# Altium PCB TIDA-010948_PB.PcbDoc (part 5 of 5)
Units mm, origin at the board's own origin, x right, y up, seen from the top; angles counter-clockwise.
Board outline 140 x 180 mm, 4 copper layers (Top Layer, Mid-Layer 1, Mid-Layer 2, Bottom Layer), stack 1.554 mm thick; 481 components, 274 nets, 1278 pads, 301 vias.
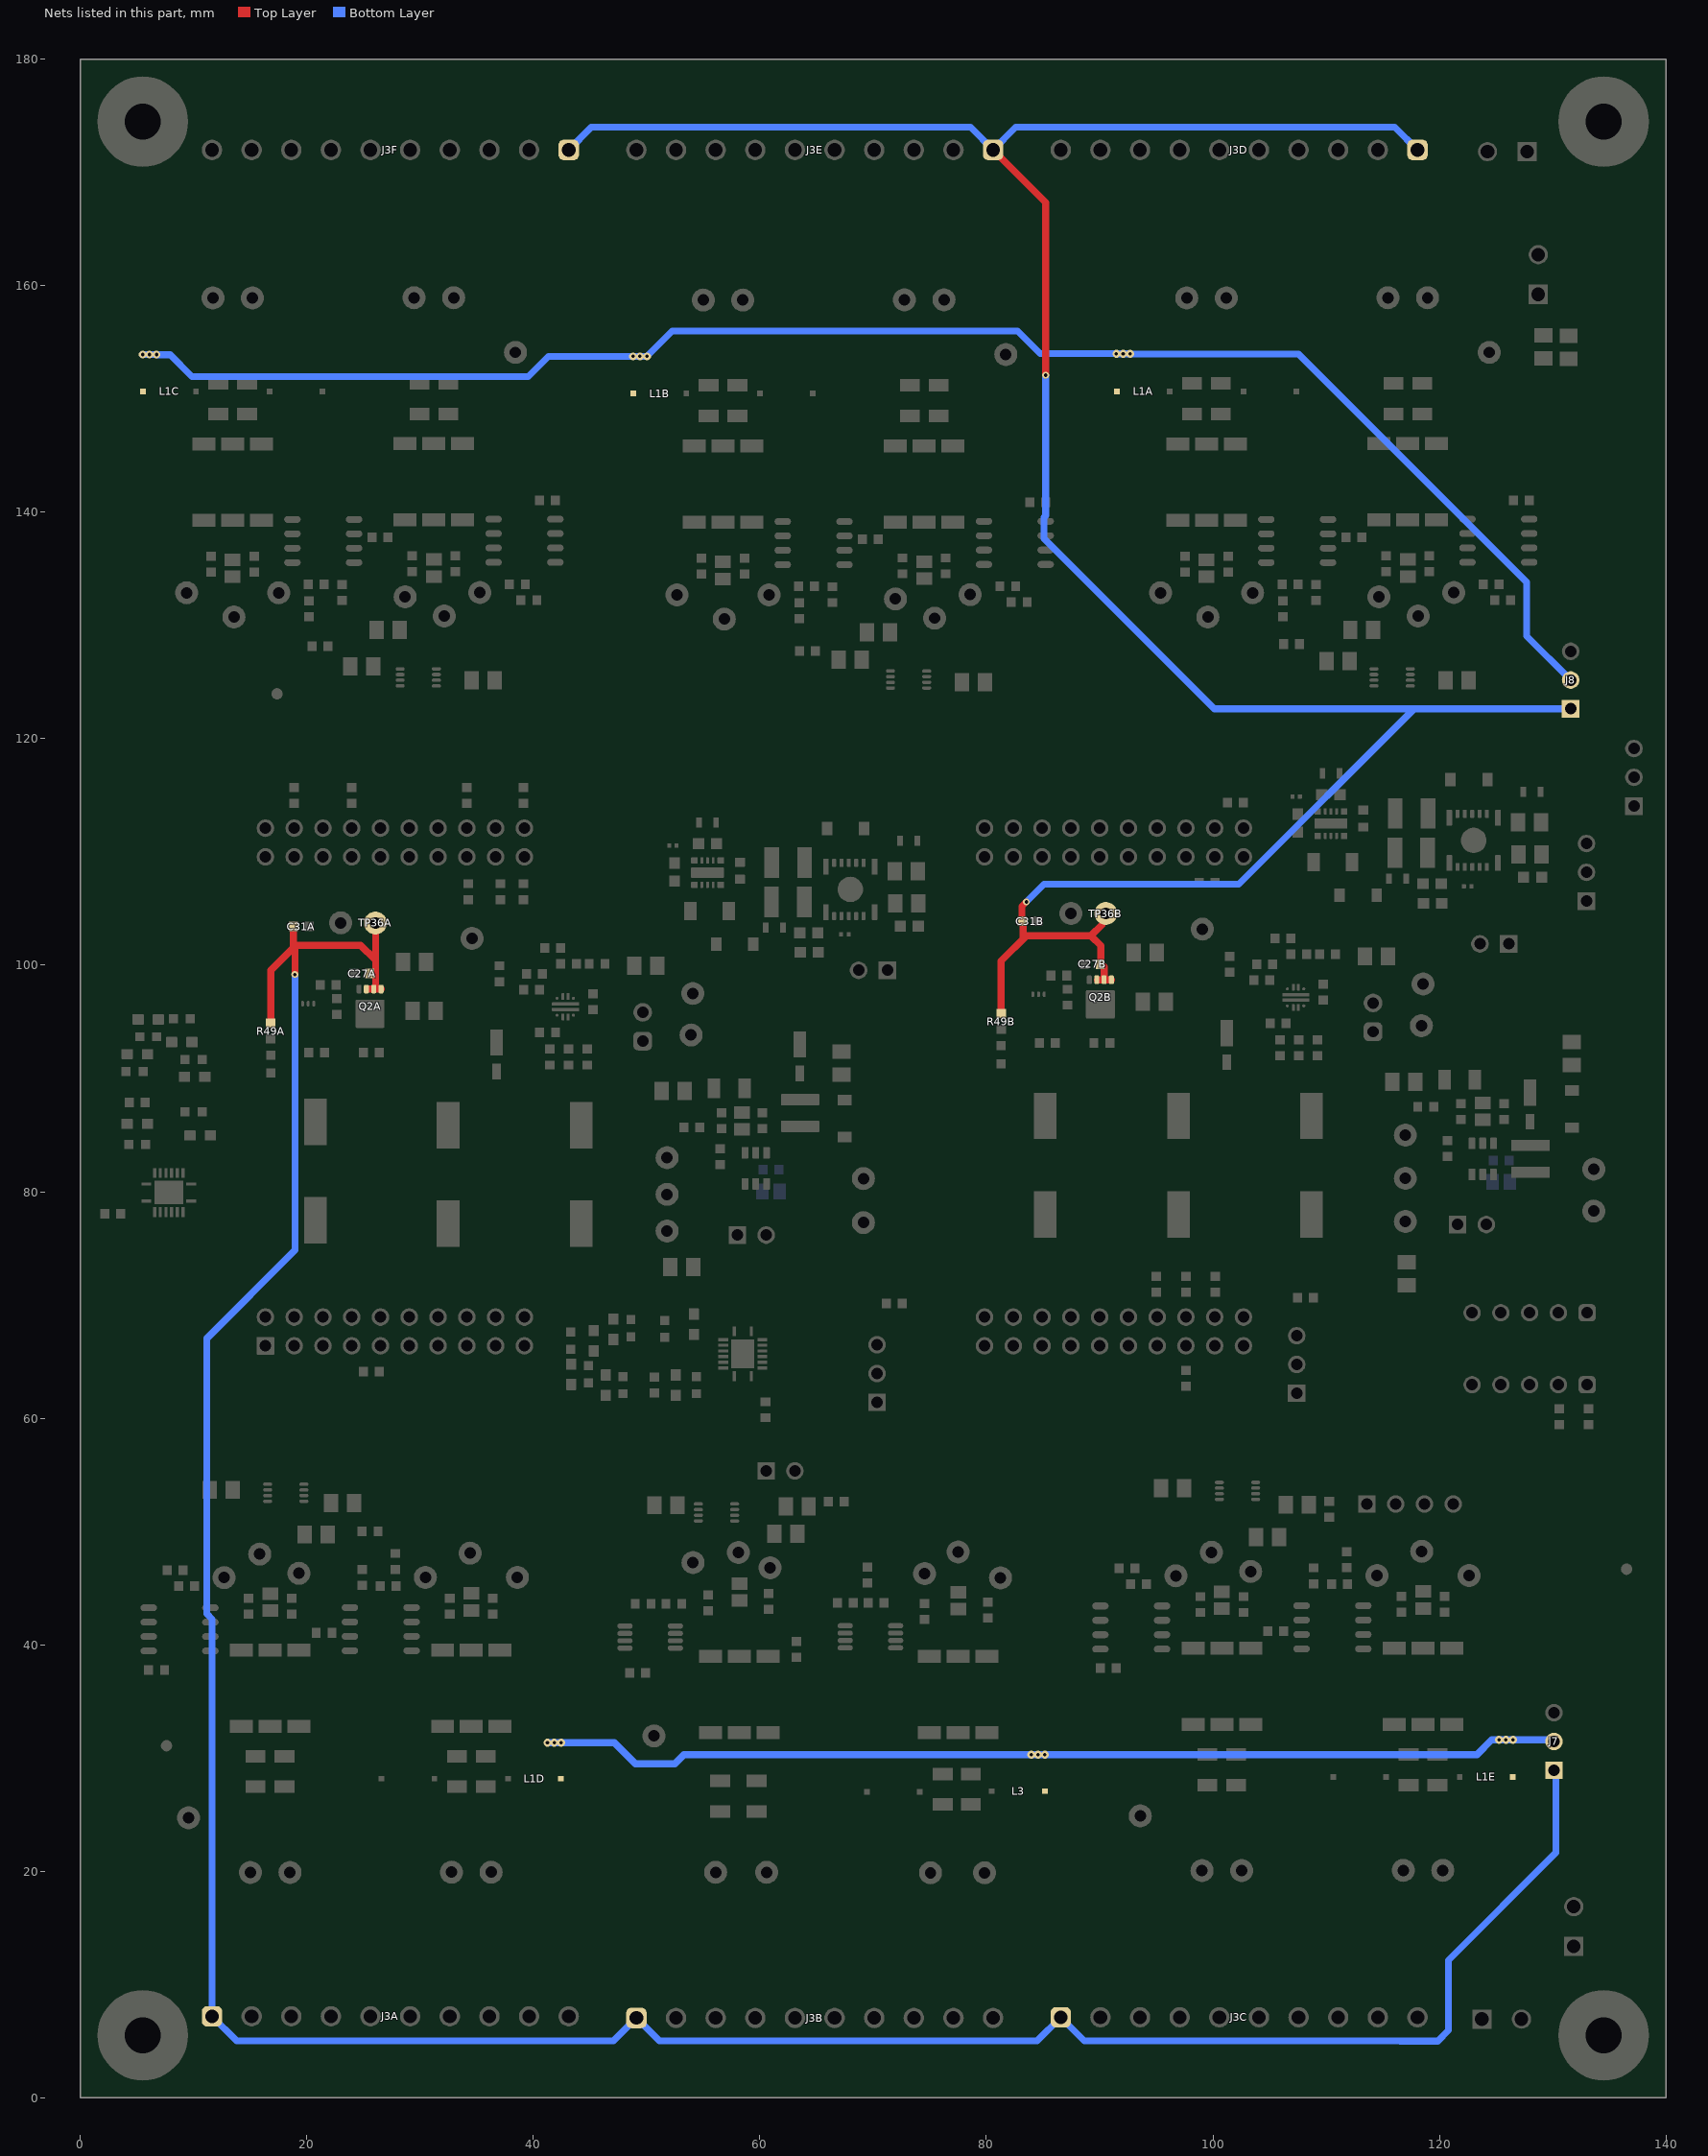
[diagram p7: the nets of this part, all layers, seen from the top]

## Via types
v1: diameter 0.457/0.457/0.457/0.457 (per signal layer), hole 0.203, Top Layer to Bottom Layer, tented both sides, 68 vias
v2: diameter 0.864, hole 0.406, Top Layer to Mid-Layer 1, 51 vias
v3: diameter 0.5, hole 0.2, Top Layer to Bottom Layer, 40 vias
v4: diameter 0.864, hole 0.406, Top Layer to Bottom Layer, 40 vias
v5: diameter 0.7, hole 0.3, Top Layer to Bottom Layer, 36 vias
v6: diameter 0.61, hole 0.3, Top Layer to Bottom Layer, 29 vias
v7: diameter 1.524, hole 0.762, Top Layer to Bottom Layer, tented both sides, 12 vias
v8: diameter 0.203, hole 0.203, Top Layer to Bottom Layer, tented both sides, 8 vias
v9: diameter 1.016, hole 0.508, Top Layer to Bottom Layer, tented both sides, 6 vias
v10: diameter 0.61, hole 0.3, Top Layer to Mid-Layer 1, 3 vias
v11: diameter 0.457, hole 0.203, Top Layer to Mid-Layer 1, tented both sides, 2 vias
v12: diameter 0.5, hole 0.2, Top Layer to Bottom Layer, tented both sides, 2 vias
v13: diameter 0.7, hole 0.203, Top Layer to Mid-Layer 1, tented both sides, 1 vias
v14: diameter 0.7, hole 0.254, Top Layer to Bottom Layer, 1 vias
v15: diameter 0.7, hole 0.254, Top Layer to Mid-Layer 1, 1 vias
v16: diameter 0.457/0.457 (per signal layer), hole 0.203, Top Layer to Mid-Layer 1, tented both sides, 1 vias

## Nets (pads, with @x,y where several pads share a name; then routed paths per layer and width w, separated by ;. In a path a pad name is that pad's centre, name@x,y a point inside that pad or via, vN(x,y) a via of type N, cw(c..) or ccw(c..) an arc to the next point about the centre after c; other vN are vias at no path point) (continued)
VOUT__ENC_4_WIRE_A: C27A.1 C31A.1 J3A.1 J3B.1 J3C.1 J7.1 Q2A.1 Q2A.2 Q2A.3 R49A.2 TP36A.1 | length 263.6
  Top Layer w0.6: v6(18.934,99.184) 18.934,101.676 19.033,101.775 ; C27A.1@25.55,99.274 26.051,99.274 ; Q2A.2@25.897,97.893 25.902,97.893 26.051,98.042 26.051,99.274 ; TP36A.1@26.051,103.738 26.051,100.515 26.051,99.274
  Top Layer w0.635: R49A.2@16.809,94.894 16.809,99.551 18.934,101.676 ; 18.817,101.559 C31A.1@18.817,103.405 ; 19.033,101.775 24.749,101.775 26.009,100.515 26.051,100.515 ; Q2A.3@25.334,97.893 Q2A.2@25.897,97.893 ; Q2A.2@25.902,97.893 Q2A.1@26.547,97.893
  Bottom Layer w0.6: v6(18.934,99.184) 18.934,74.826 11.17,67.062 11.17,42.708 11.615,42.262 J3A.1@11.615,7.181 13.797,5 47.06,5 J3B.1@49.091,7.032 51.123,5 84.477,5 J3C.1@86.567,7.09 88.657,5 116.508,5 116.516,4.992 119.862,4.992 120.806,5.936 120.806,9.781 120.796,9.79 120.796,12.135 130.301,21.64 130.301,28.726 J7.1@130.118,28.909
VOUT__ENC_4_WIRE_B: C27B.1 C31B.1 J3D.1 J3E.1 J3F.1 J8.1 Q2B.1 Q2B.2 Q2B.3 R49B.2 TP36B.1 | length 233.6
  Top Layer w0.6: J3E.1@80.591,172 85.234,167.357 v6(85.234,152.111) ; C31B.1@83.143,103.879 83.143,105.205 83.526,105.588 v6(83.526,105.591) ; 89.221,102.604 90.271,103.654 90.271,104.293 TP36B.1@90.545,104.567
  Top Layer w0.635: R49B.2@81.302,95.723 81.302,100.38 83.526,102.604 89.221,102.604 90.126,101.698 C27B.1@90.126,100.103 ; C31B.1@83.143,103.879 83.226,103.797 83.226,102.447 83.298,102.375 ; Q2B.3@89.828,98.722 Q2B.2@90.39,98.722 ; C27B.1@90.144,100.103 90.39,99.856 Q2B.2@90.39,98.722 ; Q2B.1@91.04,98.722 Q2B.2@90.39,98.722
  Bottom Layer w0.6: J3F.1@43.115,172 45.115,174 78.591,174 J3E.1@80.591,172 82.591,174 116.067,174 J3D.1@118.067,172 ; v6(83.526,105.591) 85.095,107.159 102.28,107.159 117.766,122.644 ; v6(85.234,152.111) 85.234,139.692 85.098,139.556 85.098,137.679 100.133,122.644 117.766,122.644 ; J8.1@131.592,122.644 117.766,122.644
VOUT_ENC_2_WIRE_A: J7.2 L1D.2 L1E.2 L3.2 | length 90.5
  Bottom Layer w0.635: v5@41.31,31.352 47.13,31.352 48.999,29.483 52.491,29.483 53.294,30.287 123.311,30.287 124.614,31.59 v5(125.881,31.59) v5(126.494,31.59) 126.507,31.578 129.989,31.578 J7.2@130.118,31.449
  other v5: 83.953,30.281 84.552,30.281 85.166,30.281 41.236,31.343 41.835,31.343 42.449,31.343 125.281,31.59
VOUT_ENC_2_WIRE_B: J8.2 L1A.2 L1B.2 L1C.2 | length 144
  Bottom Layer w0.6: v5(5.5,153.931) v5(6.099,153.931) v5(6.712,153.931) 6.732,153.912 7.935,153.912 9.85,151.997 39.544,151.997 41.314,153.767 v5(48.803,153.767) v5(49.402,153.767) v5(50.016,153.767) 52.249,156 82.765,156 84.748,154.017 91.382,154.017 91.387,154.012 91.449,154.012 v5@91.453,154.017 ; v5(91.477,153.993) v5(92.076,153.993) v5(92.69,153.993) ; v5@92.711,153.972 92.713,153.974 92.779,153.974 92.781,153.972 107.559,153.972 127.704,133.828 127.704,129.073 J8.2@131.592,125.184
pads on no net: FID1.1 FID2.1 FID3.1 H1.1 H2.1 H3.1 H4.1 H5.0 H6.0 H7.0 H8.0 J1.2 J1.3 J1.4 J1.6 J1.7 J1.8 J1.9 J1.10 J1.23 J1.24 J1.25 J1.26 J1.27 J1.28 J1.29 J1.30 J2.12 J2.16 J2.18 J2.34 J2.35 J2.36 J2.37 J2.38 J2.39 J2.40 J5.42 J5.45 J5.46 J5.47 J5.49 J5.50 J5.61 J5.63 J5.64 J5.65 J5.66 J6.52 J6.53 J6.54 J6.55 J6.56 J6.57 J6.58 J6.59 J6.73 J6.74 J6.75 J6.76 J6.77 J6.78 J6.79 J6.80 J7.3 J8.3 J12.4 J21.4 LBL1.0 Q2A.9@24.597,95.193 Q2A.9@24.909,95.704 Q2A.9@24.909,96.58 Q2A.9@25.247,95.193 Q2A.9@25.572,96.04 Q2A.9@25.897,95.193 Q2A.9@26.234,95.704 Q2A.9@26.234,96.58 Q2A.9@26.547,95.193 Q2B.9@89.09,96.022 Q2B.9@89.74,96.022 Q2B.9@89.403,96.533 Q2B.9@89.403,97.409 Q2B.9@90.39,96.022 Q2B.9@90.065,96.869 Q2B.9@90.728,96.533 Q2B.9@90.728,97.409 Q2B.9@91.04,96.022 Q3A.1@19.586,96.607 Q3A.2@20.111,96.607 Q3A.3@20.636,96.607 Q3B.1@84.079,97.436 Q3B.2@84.604,97.436 Q3B.3@85.129,97.436 T1A.2 T1A.5 T1B.2 T1B.5 T1C.2 T1C.5 T1D.2 T1D.5 T1E.2 T1E.5 T2A.2 T2A.5 T2B.2 T2B.5 T2C.2 T2C.5 T2D.2 T2D.5 T2E.2 T2E.5 T3.2 T3.5 T4.2 T4.5 U3.1 U5A.1 U5B.1 U5C.1 U5D.1 U5E.1 U11A.8 U11B.8 U14A.3 U14A.4 U14A.5 U14A.6 U14A.13 U14B.3 U14B.4 U14B.5 U14B.6 U14B.13

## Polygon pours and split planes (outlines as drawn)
V_BULKA on Top Layer "TOP_LAYER_V_BULKA_P082" (solid, remove dead copper, pour order 82): 40.926,99.255 40.926,91.253 32.671,91.254 32.671,99.255
V_BULKA on Top Layer "TOP_LAYER_V_BULKA_P078" (solid, remove dead copper, pour order 78): 49.589,88.122 49.589,82.788 15.361,82.788 15.361,88.122
V_BULKB on Top Layer "TOP_LAYER_V_BULKB_P084" (solid, remove dead copper, pour order 84): 79.841,89.084 113.994,89.084 113.994,83.482 110.377,83.482 79.841,83.501
GND_ENC on Top Layer "TOP_LAYER_GND_ENC_P086" (solid, remove dead copper, pour order 86): 79.854,80.402 114.061,80.402 114.061,79.067 118.562,79.067 118.562,73.237 118.66,73.139 114.061,73.139 114.061,75.036 79.876,75.036
GND_ENC on Top Layer "TOP_LAYER_GND_ENC_P079" (solid, remove dead copper, pour order 79): 48.382,80.248 48.382,77.962 52.898,77.962 52.898,72.628 15.361,72.628 15.361,80.248
GND on Top Layer "TOP_LAYER_GND_P091" (solid, remove dead copper, pour order 91): 1,4 4,1 135.1,1 139.24,5.14 139.24,175.461 135.7,179 6,179 1,174
V_BULKB on Top Layer "TOP_LAYER_V_BULKB_P095" (solid, remove dead copper, pour order 95): 105.354,99.073 105.354,91.072 97.1,91.072 97.099,99.074
V_BULKA on Bottom Layer "BOTTOM_LAYER_V_BULKA_P083" (solid, remove dead copper, pour order 83): 47.194,94.021 38.939,94.021 38.939,98.621 47.194,98.621
GND on Bottom Layer "BOTTOM_LAYER_GND_P092" (solid, remove dead copper, pour order 92): 1,174 1,4 4,1 135.1,1 139.24,5.14 139.24,175.76 136,179 6,179
NetNT8A_2 on Bottom Layer "BOTTOM_LAYER_NETNT8A_2_P080" (solid, remove dead copper, pour order 80): 29.827,92.768 29.827,97.942 21.953,97.942 21.953,92.768
NetNT8B_2 on Bottom Layer "BOTTOM_LAYER_NETNT8B_2_P088" (solid, remove dead copper, pour order 88): 86.466,92.717 86.526,92.777 86.526,98.409 95.076,98.409 95.077,98.408 95.077,92.694
GND on Bottom Layer "BOTTOM_LAYER_GND_P089" (solid, remove dead copper, pour order 89): 64.17,102.447 64.17,110.169 71.075,110.169 71.075,102.446
GND on Bottom Layer "BOTTOM_LAYER_GND_P096" (solid, remove dead copper, pour order 96): 119.534,105.941 119.534,113.662 126.438,113.662 126.438,105.94
V_BULKB on Bottom Layer "BOTTOM_LAYER_V_BULKB_P090" (solid, pour order 90): 108.595,98.71 109.9,98.71 109.9,95.974 102.794,95.974 102.794,98.456 104.35,98.456 107.849,101.955 108.595,101.955
GND_EXT on Mid-Layer 1 "MID-LAYER_1_GND_EXT_P085" (solid, remove dead copper, pour order 85): 6,179 1,174 1,7.029 7.029,1 133.576,1 139.24,7.029 139.24,7.051 139.24,175.76 136,179
GND_ENC on Mid-Layer 2 "MID-LAYER_2_GND_ENC_P087" (solid, remove dead copper, pour order 87): 6,179 1,174 1,8.105 7.581,1.524 133.162,1.524 138.645,7.007 138.645,176.24 135.885,179

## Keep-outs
Keep-Out Layer:
  text ".Layer_Name" at 14.656,-21.806 h0.89

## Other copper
Top Layer:
  region net GND_ENC: 28.181,25.552 26.191,25.552 26.191,24.311 28.181,24.311
  region net GND_ENC: 71.05,24.353 69.061,24.353 69.061,23.112 71.05,23.112
  region net GND_ENC: 112.222,25.703 110.233,25.703 110.233,24.462 112.222,24.462
  region net GND_ENC: 107.737,150.022 107.737,148.033 108.978,148.033 108.978,150.022
  region net GND_ENC: 65.079,147.867 63.09,147.867 63.09,146.626 65.079,146.626
  region net GND_ENC: 21.777,148.071 19.788,148.071 19.788,146.83 21.777,146.83
  rectangle net VOUT_ENC_2_WIRE_B: 5.103,153.301 7.092,154.542
  rectangle net VOUT_ENC_2_WIRE_B: 91.102,153.297 93.091,154.538
  rectangle net VOUT_ENC_2_WIRE_B: 48.403,153.105 50.392,154.346
  rectangle net VOUT_ENC_2_WIRE_A: 40.854,30.768 42.843,32.009
  rectangle net VOUT_ENC_2_WIRE_A: 83.583,29.679 85.572,30.92
  rectangle net VOUT_ENC_2_WIRE_A: 124.899,30.952 126.888,32.194
  region net V_BULKA: 41.434,95.959 41.434,96.213 40.799,96.848 40.799,95.324
  text ".Layer_Name" at 14.656,-21.806 h0.89
Bottom Layer:
  text ".Layer_Name" at 14.656,-21.806 h0.89

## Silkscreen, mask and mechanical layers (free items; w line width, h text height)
Top Overlay:
  lines w0.254: 35.396,141.074 35.396,140.686 ; 35.737,142.099 35.737,141.028 35.396,140.686 ; 35.83,140.686 35.396,140.686 ; 58.261,57.791 59.696,57.791 60.421,57.067 60.421,57.052 ; 61.828,128.355 62.33,128.355 63.47,129.495 ; 68.64,63.821 66.994,63.821 66.994,66.485 66.993,66.486 68.64,66.486 ; 72.041,61.367 73.689,61.367 73.688,61.368 73.688,64.031 72.041,64.031 ; 79.019,140.711 79.019,140.323 ; 79.361,141.736 79.361,140.664 79.019,140.323 ; 79.453,140.323 79.019,140.323 ; 102.839,126.687 102.858,126.687 104.954,128.783 ; 104.512,128.783 104.954,128.783 ; 104.954,128.398 104.954,128.783 ; 105.669,61.887 104.022,61.887 104.022,64.55 104.021,64.551 105.669,64.551 ; 109.039,64.647 110.687,64.647 110.686,64.648 110.686,67.312 109.039,67.312 ; 111.46,55.643 113.473,55.643 113.473,54.328 ; 115.669,54.178 115.669,55.825 118.333,55.825 118.334,55.826 118.333,54.178 ; 118.936,54.178 118.936,55.825 121.6,55.825 121.6,55.826 121.6,54.178 ; 121.409,140.925 121.409,140.537 ; 121.75,141.95 121.75,140.878 121.409,140.537 ; 121.843,140.537 121.409,140.537 ; 132.106,28.391 133.754,28.391 133.753,28.392 133.753,31.056 132.106,31.056 ; 132.118,31.534 133.765,31.534 133.764,31.534 133.764,34.198 132.118,34.198 ; 133.674,122.168 134.73,122.168 134.73,124.833 133.674,124.833 ; 133.674,125.184 134.73,125.184 134.73,127.849 133.674,127.849 ; 135.029,105.224 136.085,105.224 136.085,107.888 135.029,107.888 ; 135.029,108.489 136.085,108.489 136.085,111.153 135.029,111.153 ; 135.356,113.706 134.3,113.706 134.3,116.37 135.356,116.37 ; 135.356,116.841 134.3,116.841 134.3,119.506 135.356,119.506
  text "This document can handle board shapes up to about 13in on a side." at 355.153,271.019 h0.89
  text "To re-size the board shape, do the following:" at 356.55,264.717 h0.89
  text "Select lines on M1 Board Outline and delete (easy in single layer mode...shift+s)" at 358.074,261.566 h0.89
  text "Draw a rectangle using lines (example will be for a 4\" x 6\" board" at 358.074,258.415 h0.89
  text "Enter Place Line mode (keyboard pl)" at 363.408,255.264 h0.89
  text "keyboard jo to jump to origin, hit enter" at 363.408,252.113 h0.89
  text "keyboard jl to jump to location, set x to 6000, hit enter twice" at 363.408,248.961 h0.89
  text "keyboard jl to jump to location, set x to 6000 and y to 4000, hit enter twice" at 363.408,245.81 h0.89
  text "keyboard jl to jump to location, set x to 0 and y to 4000, hit enter twice" at 363.408,242.659 h0.89
  text "keyboard jo to jump to origin, hit enter" at 363.408,239.508 h0.89
  text "Hit ESC twice to exit place line mode" at 363.408,236.357 h0.89
  text "Select lines on M1 Board Outline" at 358.074,232.698 h0.89
  text "Menu Design|Board Shape|Define from Selected Objects (keyboard dsd)" at 358.074,230.055 h0.89
  text "If you re-size the board, don't forget to move the drill table strings on the" at 355.153,221.946 h0.89
  text "Drill Drawing Layer...they should be just to the right of your board shape" at 360.055,219.254 h0.89
  text "+   -" at 128.147,177.929 h0.89 r180
  text "GND" at 11.186,169.148 h0.89 r270
  text "I" at 14.773,168.61 h0.89 r270
  text "B" at 18.199,168.61 h0.89 r270
  text "C_P" at 35.768,168.61 h0.89 r270
  text "C_N" at 39.193,168.61 h0.89 r270
  text "11V0/12V0" at 42.59,168.61 h0.89 r270
  text "5V0" at 24.945,168.457 h0.89 r270
  text "D_N" at 32.056,168.457 h0.89 r270
  text "A" at 21.767,168.408 h0.89 r270
  text "CH6" at 44.847,168.408 h0.89 r270
  text "GND" at 48.559,168.408 h0.89 r270
  text "I" at 52.243,168.408 h0.89 r270
  text "B" at 55.55,168.408 h0.89 r270
  text "A" at 59.109,168.408 h0.89 r270
  text "5V0" at 62.821,168.408 h0.89 r270
  text "D_P" at 65.936,168.408 h0.89 r270
  text "D_N" at 69.899,168.408 h0.89 r270
  text "C_P" at 73.303,168.408 h0.89 r270
  text "C_N" at 76.848,168.408 h0.89 r270
  text "11V0/12V0" at 80.279,168.408 h0.89 r270
  text "CH5" at 82.887,168.408 h0.89 r270
  text "GND" at 86.375,168.408 h0.89 r270
  text "I" at 89.724,168.408 h0.89 r270
  text "B" at 93.408,168.408 h0.89 r270
  text "A" at 96.757,168.408 h0.89 r270
  text "5V0" at 100.358,168.408 h0.89 r270
  text "D_P" at 103.808,168.408 h0.89 r270
  text "D_N" at 107.352,168.408 h0.89 r270
  text "C_P" at 110.701,168.408 h0.89 r270
  text "C_N" at 114.329,168.408 h0.89 r270
  text "11V0/12V0" at 117.712,168.408 h0.89 r270
  text "CH4" at 120.312,168.408 h0.89 r270
  text "D_P" at 28.764,168.387 h0.89 r270
  text "VIN_24V0" at 124.565,167.307 h0.89
  text "+   -" at 134.667,158.807 h0.89 r90
  text "VIN_5V0" at 124.296,157.781 h0.89 r90
  text "4 WIRE RS485" at 136.253,128.611 h0.89 r90
  text "2 WIRE RS485" at 138.066,122.398 h0.89 r90
  text "Single EXT 24V" at 131.578,116.818 h0.58
  text "Dual EXT 24V" at 131.745,112.837 h0.64
  text "Single EXT 5V" at 136.505,107.847 h0.58
  text "Dual EXT 5V" at 136.672,103.865 h0.64
  text "12V0 ENC" at 122.115,99.186 h0.89
  text "Bypass fuse" at 111.67,98.661 h0.64
  text "Bypass fuse" at 47.128,97.943 h0.64
  text "12V0 ENC" at 67.533,96.889 h0.89
  text "12V0 ENC" at 120.376,73.927 h0.89
  text "12V0 ENC" at 56.846,72.762 h0.89
  text "LS_EN" at 65.085,67.865 h0.89
  text "RS485_EN" at 111.902,65.948 h0.89
  text "RS485_DIS" at 111.496,62.232 h0.89
  text "LS_DIS" at 72.767,59.5 h0.89
  text "R276" at 58.064,58.196 h0.89
  text "eQEP" at 119.277,56.496 h0.89
  text "R128" at 111.161,56.343 h0.89
  text "RS485" at 114.852,56.343 h0.89
  text "'.PRJ_Number'.PCB_Rev" at 135.102,41.973 h0.89 r90
  text "4 WIRE RS485" at 136.729,31.792 h0.89 r90
  text "2 WIRE RS485" at 136.729,21.792 h0.89 r90
  text "VIN_5V0" at 127.766,14.377 h0.89 r90
  text "+   -" at 138.038,12.877 h0.89 r90
  text "VIN_24V0" at 121.513,11.081 h0.89
  text "CH1" at 9.848,10.691 h0.89 r90
  text "11V0/12V0" at 11.838,10.691 h0.89 r90
  text "C_N" at 15.517,10.691 h0.89 r90
  text "C_P" at 18.957,10.691 h0.89 r90
  text "D_N" at 22.503,10.691 h0.89 r90
  text "D_P" at 26.085,10.691 h0.89 r90
  text "5V0" at 29.431,10.691 h0.89 r90
  text "A" at 32.818,10.691 h0.89 r90
  text "B" at 36.329,10.691 h0.89 r90
  text "I" at 39.716,10.691 h0.89 r90
  text "GND" at 43.262,10.691 h0.89 r90
  text "CH2" at 47.039,10.691 h0.89 r90
  text "11V0/12V0" at 49.164,10.691 h0.89 r90
  text "C_N" at 52.737,10.691 h0.89 r90
  text "C_P" at 56.248,10.691 h0.89 r90
  text "D_N" at 59.954,10.691 h0.89 r90
  text "D_P" at 63.376,10.691 h0.89 r90
  text "5V0" at 66.9,10.691 h0.89 r90
  text "A" at 70.18,10.691 h0.89 r90
  text "B" at 73.673,10.691 h0.89 r90
  text "I" at 77.184,10.691 h0.89 r90
  text "GND" at 80.713,10.691 h0.89 r90
  text "CH3" at 84.472,10.691 h0.89 r90
  text "11V0/12V0" at 86.491,10.691 h0.89 r90
  text "C_N" at 90.24,10.691 h0.89 r90
  text "C_P" at 93.893,10.691 h0.89 r90
  text "D_N" at 97.28,10.691 h0.89 r90
  text "D_P" at 100.968,10.691 h0.89 r90
  text "5V0" at 104.403,10.691 h0.89 r90
  text "A" at 107.719,10.691 h0.89 r90
  text "B" at 111.425,10.691 h0.89 r90
  text "I" at 115.06,10.691 h0.89 r90
  text "GND" at 118.394,10.691 h0.89 r90
  text "+   -" at 123.149,0.876 h0.89
  text ".Layer_Name" at 14.656,-21.806 h0.89
Bottom Overlay:
  text ".Layer_Name" at 14.656,-21.806 h0.89
Top Paste:
  text ".Layer_Name" at 14.656,-21.806 h0.89
Bottom Paste:
  text ".Layer_Name" at 14.656,-21.806 h0.89
Top Solder:
  text ".Layer_Name" at 14.656,-21.806 h0.89
  text ".Layer_Name" at 14.656,-21.806 h0.89
Bottom Solder:
  text ".Layer_Name" at 14.656,-21.806 h0.89
Drill Guide:
  text ".Layer_Name" at 14.656,-21.806 h0.89
M1 Board Outline:
  lines w0.254: 0,0 140.05,0 140,180 0,180 0,0
  text ".Layer_Name" at 14.656,-21.806 h0.89
M2 Board Dimensions:
  rectangle: 3.175,-10.16 12.7,-6.985
  rectangle: 0,-6.985 3.175,-3.81
  lines w0.178: 0,-6.985 25.4,-6.985 ; 3.175,-10.16 3.175,-3.81 ; 6.35,-10.16 6.35,-3.81 ; 12.7,-10.16 12.7,-3.81 ; 19.05,-10.16 19.05,-3.81 ; 0,-10.16 0,-3.81 25.4,-3.81 25.4,-10.16 0,-10.16
  text ".Layer_Name" at 14.656,-21.806 h0.89
M3 3D STEP Top:
  text ".Layer_Name" at 14.656,-21.806 h0.89
M4 3D STEP Bottom:
  text ".Layer_Name" at 14.656,-21.806 h0.89
M5 Assembly Top:
  lines w0.254: -7.417,-23.626 160.223,-23.626 ; -7.417,-18.462 160.274,-18.462 ; -7.417,-13.297 -7.417,-28.791 94.31,-28.791 160.274,-28.791 160.274,-13.297 -7.404,-13.297 -7.404,-28.791 32.614,-28.791 ; 55.194,-28.791 55.194,-13.297 ; 87.376,-18.462 87.376,-13.297 ; 108.712,-18.462 108.712,-13.297 ; 124.511,-28.956 124.511,-23.804
  text "COMPONENTS MARKED 'DNP' SHOULD NOT BE POPULATED." at 29.299,-8.09 h0.89
  text "ASSEMBLY VARIANT:" at 29.286,-11.024 h0.89
  text ".VariantName" at 55.601,-11.024 h0.89
  text "PCB VIEWED FROM TOP SIDE" at -5.804,-16.654 h0.89
  text "BOARD #:" at 57.099,-16.654 h0.89
  text ".PRJ_Number" at 70.955,-16.654 h0.89
  text "REV:" at 92.405,-16.654 h0.89
  text ".PCB_Rev" at 99.809,-16.654 h0.89
  text "SVN REV:" at 113.69,-16.654 h0.89
  text ".VersionControl_RevNumber" at 126.543,-16.654 h0.89
  text "PLOT NAME =" at -5.804,-27.034 h0.89
  text ".plot_File_Name" at 14.656,-27.034 h0.89
  text "GENERATED    :" at 57.15,-27.034 h0.89
  text ".Print_Date" at 79.235,-27.034 h0.89
  text ".Print_Time" at 97.752,-27.034 h0.89
  text "TEXAS INSTRUMENTS" at 129.87,-27.034 h0.89
M6 Assembly Bottom:
  lines w0.254: -7.429,-18.474 160.261,-18.474 ; -7.379,-23.639 160.261,-23.639 ; 28.334,-28.969 28.334,-23.817 ; 44.133,-18.474 44.133,-13.31 ; 65.468,-18.474 65.468,-13.31 ; 97.65,-28.804 97.65,-13.31 ; 120.231,-28.804 160.249,-28.804 160.249,-13.31 -7.429,-13.31 -7.429,-28.804 58.534,-28.804 160.261,-28.804 160.261,-13.31
  text "COMPONENTS MARKED 'DNP' SHOULD NOT BE POPULATED." at 154.991,-8.077 h0.89
  text ".VariantName" at 128.473,-11.024 h0.89
  text "ASSEMBLY VARIANT:" at 154.864,-11.024 h0.89
  text ".VersionControl_RevNumber" at 26.302,-16.667 h0.89
  text "SVN REV:" at 39.154,-16.667 h0.89
  text ".PCB_Rev" at 53.035,-16.667 h0.89
  text "REV:" at 60.439,-16.667 h0.89
  text ".PRJ_Number" at 81.89,-16.667 h0.89
  text "BOARD #:" at 95.745,-16.667 h0.89
  text "PCB VIEWED FROM BOTTOM SIDE" at 158.648,-16.667 h0.89
  text "TEXAS INSTRUMENTS" at 22.974,-27.047 h0.89
  text ".Print_Time" at 55.093,-27.047 h0.89
  text ".Print_Date" at 73.609,-27.047 h0.89
  text "GENERATED    :" at 95.694,-27.047 h0.89
  text ".plot_File_Name" at 138.189,-27.047 h0.89
  text "PLOT NAME =" at 158.648,-27.047 h0.89
M9 Title Sheet:
  drawing of 56 lines, arcs and shapes, not listed
  text "1" at 26.882,339.887 h0.72
  text "2" at 111.354,339.887 h0.72
  text "3" at 195.936,339.887 h0.72
  text "4" at 280.645,339.887 h0.72
  text "5" at 365.1,339.887 h0.72
  text "6" at 449.809,339.887 h0.72
  text "A" at -11.76,294.726 h0.72
  text "A" at 488.62,294.726 h0.72
  text "B" at -11.76,199.476 h0.72
  text "B" at 488.62,199.476 h0.72
  text "C" at -11.76,104.226 h0.72
  text "C" at 488.62,104.226 h0.72
  text "D" at -11.76,8.976 h0.72
  text "D" at 488.62,8.976 h0.72
  text "PROJECT TITLE:" at 410.032,6.817 h0.72
  text ".PRJ_Title" at 411.302,3.431 h0.72
  text "DESIGNED FOR:" at 410.032,-0.828 h0.72
  text ".PRJ_Customer" at 411.302,-4.384 h0.72
  text "FILE NAME:" at 410.032,-8.448 h0.72
  text ".PCB_File_Name_No_Path" at 411.302,-11.496 h0.72
  text "Texas Instruments (TI) and/or its licensors do not warrant the accuracy or completeness of this specification" at 283.807,-15.607 h0.72
  text "ENGINEER:" at 410.032,-15.814 h0.72
  text "LAYOUT BY:" at 448.259,-15.814 h0.72
  text "or any information contained therein. TI and/or its licensors do not warrant that this design will meet" at 282.664,-18.469 h0.72
  text ".PRJ_Engineer" at 411.302,-19.751 h0.72
  text ".PCB_Layout" at 449.542,-19.751 h0.72
  text "the specifications, will be suitable for your application or fit for any particular purpose, or will operate in" at 282.664,-21.33 h0.72
  text ".Layer_Name" at 14.656,-21.806 h0.72
  text "ALTIUM DESIGNER VERSION:" at 448.259,-23.688 h0.72
  text "an implementation. TI and/or its licensors do not warrant that the design is production worthy. You should" at 282.664,-24.192 h0.72
  text "completely validate and test your design implementation to confirm the system functionality for your application." at 283.807,-27.054 h0.72
  text ".print_Scale" at 411.302,-27.075 h0.72
  text ".Application_BuildNumber" at 449.542,-27.075 h0.72
  text "1" at 26.882,-33.493 h0.72
  text "2" at 111.354,-33.493 h0.72
  text "3" at 195.936,-33.493 h0.72
  text "4" at 280.645,-33.493 h0.72
  text "5" at 365.1,-33.493 h0.72
  text "6" at 449.809,-33.493 h0.72
M10 Fab Notes:
  drawing of 189 lines, arcs and shapes, not listed
  text "DESIGN INFORMATION" at 436.322,161.675 h0.89
  text "MIN. TRACK WIDTH:" at 419.95,158.319 h0.89
  text "8" at 447.794,158.32 h0.89
  text "MIL" at 451.725,158.319 h0.89
  text "MIN. CLEARANCE:" at 419.95,155.167 h0.89
  text "MIL" at 451.725,155.167 h0.89
  text "7.874" at 443.475,155.05 h0.89
  text "MIN. VIA PAD SIZE:" at 419.95,152.014 h0.89
  text "24" at 447.033,152.014 h0.89
  text "MIL" at 451.725,152.014 h0.89
  text "0.05mm (2MIL)" at 437.603,148.714 h0.89
  text "MINIMUM ANNULAR RING" at 411.587,148.506 h0.89
  text "EXTERNAL" at 455.586,148.506 h0.89
  text "PER" at 416.667,145.708 h0.89
  text "IPC-D-275 CLASS 2 LEVEL C" at 422.255,145.708 h0.89
  text "MIL, HOLES" at 460.056,143.156 h0.89
  text "+/-" at 450.088,142.938 h0.89
  text "+/-" at 471.78,142.938 h0.89
  text "REGISTRATION TOLERANCES:" at 411.587,142.911 h0.89
  text "METAL" at 442.062,142.911 h0.89
  text "5" at 456.697,142.911 h0.89
  text "3" at 477.855,142.911 h0.89
  text "MIL" at 480.808,142.911 h0.89
  text "HOLE SIZE TOLERANCE (UNLESS OTHERWISE SPECIFIED):" at 411.587,140.414 h0.89
  text "+/-" at 471.78,140.341 h0.89
  text "3" at 477.855,140.314 h0.89
  text "MIL" at 480.808,140.314 h0.89
  text "MATERIAL:" at 409.688,136.818 h0.89
  text "FR-4 High Tg" at 434.744,133.553 h0.89
  text "X" at 431.075,133.35 h0.89
  text "FR-4" at 420.382,133.235 h0.89
  text "OTHER" at 458.177,133.235 h0.89
  text "X" at 458.25,129.775 h0.89
  text "62 MIL (1.6mm) +/-10%" at 428.512,129.602 h0.89
  text "THICKNESS:" at 411.587,129.394 h0.89
  text "OTHER" at 461.149,129.394 h0.89
  text "TOLERANCE:" at 411.587,125.88 h0.89
  text "X" at 433.133,125.88 h0.89
  text "ANSI IPC-6012 TYPE 3 CLASS 2" at 437.654,125.88 h0.89
  text "OTHER +/-" at 437.654,122.218 h0.89
  text "BOW & TWIST:" at 411.587,118.53 h0.89
  text "X" at 433.133,118.53 h0.89
  text "ANSI IPC-6012 TYPE 3 CLASS 2" at 437.654,118.53 h0.89
  text "OTHER +/-" at 437.654,114.804 h0.89
  text "DRILLING:" at 409.688,111.486 h0.89
  text "NC_DRILL FILES" at 454.418,108.815 h0.89
  text "REFERENCE:" at 411.587,108.715 h0.89
  text "X" at 428.281,108.712 h0.89
  text "AS SHOWN" at 432.802,108.715 h0.89
  text "X" at 451.167,108.715 h0.89
  text "OTHER" at 461.987,105.101 h0.89
  text "PTH COPPER THICKNESS:" at 411.579,105.012 h0.89
  text "X" at 440.516,105.012 h0.89
  text "20-30 um" at 443.767,105.012 h0.89
  text "BOARD FINISH:" at 409.688,101.263 h0.89
  text "SILKSCREEN:" at 413.631,98.466 h0.89
  text "X" at 437.959,98.466 h0.89
  text "TOP" at 440.93,98.466 h0.89
  text "X" at 450.913,98.466 h0.89
  text "BOTTOM" at 453.91,98.466 h0.89
  text "SILKSCREEN COLOR:" at 413.631,94.524 h0.89
  text "X" at 437.933,94.524 h0.89
  text "WHITE" at 440.93,94.524 h0.89
  text "OTHER" at 453.91,94.524 h0.89
  text "X" at 441.261,90.88 h0.89
  text "GREEN" at 444.258,90.88 h0.89
  text "OTHER" at 459.955,90.88 h0.89
  text "SOLDER RESIST COLOR:" at 413.631,90.706 h0.89
  text "X" at 441.261,86.962 h0.89
  text "MATTE" at 444.258,86.962 h0.89
  text "SEMI-GLOSS" at 459.943,86.946 h0.89
  text "IMMERSION GOLD (ENIG)" at 436.638,82.574 h0.89
  text "ENEPIG" at 470.611,82.39 h0.89
  text "SURFACE FINISH:" at 409.688,82.365 h0.89
  text "X" at 432.117,82.365 h0.89
  text "IMM. TIN/SILVER OR EQUIV" at 418.059,78.877 h0.89
  text "OTHER" at 454.418,78.777 h0.89
  text "ARRAY/PANEL:" at 409.688,74.831 h0.89
  text "CUT AND TRIM PER M1 BOARD OUTLINE" at 436.638,74.622 h0.89
  text "N.C. ROUTE" at 436.638,71.168 h0.89
  text "X" at 454.113,71.168 h0.89
  text "V. SCORE" at 458.634,71.168 h0.89
  text "CERTIFICATION:" at 409.688,67.888 h0.89
  text "MATERIALS AND WORKMANSHIP FOR ALL PCBS" at 428.103,67.888 h0.89
  text "TO MEET OR EXCEED THE REQUIREMENTS OF:" at 428.103,65.499 h0.89
  text "X" at 418.896,62.232 h0.89
  text "ANSI IPC-A-600F CLASS ->" at 422.147,62.232 h0.89
  text "X" at 464.006,62.232 h0.89
  text "2" at 466.8,62.232 h0.89
  text "1" at 458.799,62.194 h0.89
  text "3" at 475.792,62.194 h0.89
  text "X" at 439.521,58.481 h0.89
  text "RoHS" at 442.772,58.481 h0.89
  text "OTHER" at 459.14,58.481 h0.89
  text "PER ORDER" at 469.225,58.481 h0.89
  text "ALL BOARDS MUST MEET OR EXCEED UL94-V0 REQUIREMENTS." at 410.388,54.574 h0.89
  text "PCB MUST BEAR THE UL94V-0 UL REGISTERED MATERIAL ID NUMBER" at 410.388,51.626 h0.89
  text "ADDITIONAL REQUIREMENTS:" at 409.688,47.322 h0.89
  text "MICROSECTION:" at 411.587,44.601 h0.89
  text "YES" at 434.593,44.601 h0.89
  text "REQUIRED" at 456.475,40.935 h0.89
  text "BARE BOARD ELEC. TEST:" at 411.587,40.863 h0.89
  text "NONE" at 444.753,40.863 h0.89
  text "X" at 453.478,40.863 h0.89
  text "PER ORDER" at 471.512,40.863 h0.89
  text "XX MIL VIAS REQUIRE NON-CONDUCTIVE FILL AND PLANARIZE" at 415.858,35.657 h0.89
  text "XX MIL VIAS REQUIRE CONDUCTIVE FILL AND PLANARIZE" at 416.062,33.016 h0.89
  text "OUTER XX MIL TRACES REQUIRE 50 OHM SINGLE-ENDED IMPEDANCE" at 416.037,28.866 h0.89
  text "LAYER 2 & 3 (INNER LAYERS) XX MIL WIDE, XX MIL SPACE / TRACES REQUIRE 100 OHM DIFFERENTIAL IMPEDANCE" at 415.833,22.879 h0.89
  text ".Layer_Name" at 14.656,-21.806 h0.89
M11 Gerber Information:
  lines w0.254: -7.417,-23.626 160.223,-23.626 ; -7.417,-18.462 160.274,-18.462 ; -7.417,-13.297 -7.417,-28.791 94.31,-28.791 160.274,-28.791 160.274,-13.297 -7.404,-13.297 -7.404,-28.791 32.614,-28.791 ; 55.194,-28.791 55.194,-13.297 ; 87.376,-18.462 87.376,-13.297 ; 108.712,-18.462 108.712,-13.297 ; 124.511,-28.956 124.511,-23.804
  text "ALL ARTWORK VIEWED FROM TOP SIDE" at -5.804,-16.654 h0.89
  text "BOARD #:" at 57.099,-16.654 h0.89
  text ".PRJ_Number" at 70.955,-16.654 h0.89
  text "REV:" at 92.405,-16.654 h0.89
  text ".PCB_Rev" at 99.809,-16.654 h0.89
  text "SVN REV:" at 113.69,-16.654 h0.89
  text ".VersionControl_RevNumber" at 126.543,-16.654 h0.89
  text "LAYER NAME =" at -5.804,-21.806 h0.89
  text "PLOT NAME =" at -5.804,-27.034 h0.89
  text ".plot_File_Name" at 14.656,-27.034 h0.89
  text "GENERATED    :" at 57.15,-27.034 h0.89
  text ".Print_Date" at 79.235,-27.034 h0.89
  text ".Print_Time" at 97.752,-27.034 h0.89
  text "TEXAS INSTRUMENTS" at 129.87,-27.034 h0.89
M12 Stackup:
  drawing of 306 lines, arcs and shapes, not listed
  text "Layer" at 370.168,333.724 h0.72
  text "Name" at 375.381,333.724 h0.72
  text "Material" at 386.865,333.724 h0.72
  text "Thickness" at 397.505,333.724 h0.72
  text "Constant" at 405.612,333.724 h0.72
  text "Board Layer Stack" at 412.754,333.724 h0.72
  text "Top Overlay" at 375.381,332.276 h0.72
  text "Top Solder" at 375.381,330.828 h0.72
  text "Solder Resist" at 386.865,330.828 h0.72
  text "0.40mil" at 397.505,330.828 h0.72
  text "3.5" at 405.612,330.828 h0.72
  text "1" at 370.168,329.38 h0.72
  text "Top Layer" at 375.381,329.38 h0.72
  text "1.40mil" at 397.505,329.38 h0.72
  text "Dielectric2" at 375.381,327.932 h0.72
  text "FR-4" at 386.865,327.932 h0.72
  text "10.00mil" at 397.505,327.932 h0.72
  text "4.2" at 405.612,327.932 h0.72
  text "2" at 370.168,326.485 h0.72
  text "Mid-Layer 1" at 375.381,326.485 h0.72
  text "1.40mil" at 397.505,326.485 h0.72
  text "Dielectric1" at 375.381,325.037 h0.72
  text "FR-4 High Tg" at 386.865,325.037 h0.72
  text "35.57mil" at 397.505,325.037 h0.72
  text "4.2" at 405.612,325.037 h0.72
  text "3" at 370.168,323.589 h0.72
  text "Mid-Layer 2" at 375.381,323.589 h0.72
  text "1.40mil" at 397.505,323.589 h0.72
  text "Dielectric3" at 375.381,322.141 h0.72
  text "FR-4" at 386.865,322.141 h0.72
  text "10.00mil" at 397.505,322.141 h0.72
  text "4.2" at 405.612,322.141 h0.72
  text "4" at 370.168,320.693 h0.72
  text "Bottom Layer" at 375.381,320.693 h0.72
  text "1.40mil" at 397.505,320.693 h0.72
  text "Bottom Solder" at 375.381,319.246 h0.72
  text "Solder Resist" at 386.865,319.246 h0.72
  text "0.40mil" at 397.505,319.246 h0.72
  text "3.5" at 405.612,319.246 h0.72
  text "Bottom Overlay" at 375.381,317.798 h0.72
  text ".Layer_Name" at 14.656,-21.806 h0.89
M13 Component Bodies Top:
  text ".Layer_Name" at 14.656,-21.806 h0.89
M14 Component Bodies Bottom:
  text ".Layer_Name" at 14.656,-21.806 h0.89
M15 Courtyards Top:
  text ".Layer_Name" at 14.656,-21.806 h0.89
M16 Courtyards Bottom:
  text ".Layer_Name" at 14.656,-21.806 h0.89
Drill Drawing:
  circle w0.254: c280.451,315.038 r0.241
  circle w0.254: c280.451,315.038 r0.402
  circle w0.254: c280.451,313.228 r0.402
  lines w0.254: 280.049,317.25 280.853,317.25 280.451,316.445 280.049,317.25 ; 280.049,318.255 280.853,318.255 280.853,319.06 280.049,319.06 280.049,318.255 ; 280.049,320.065 280.451,320.266 280.853,320.065 280.652,320.467 280.853,320.869 280.451,320.668 280.049,320.869 280.25,320.467 280.049,320.065 ; 280.049,321.875 280.049,322.076 280.25,322.277 280.049,322.478 280.049,322.679 280.25,322.679 280.451,322.478 280.652,322.679 280.853,322.679 280.853,322.478 280.652,322.277 280.853,322.076 280.853,321.875 280.652,321.875 280.451,322.076 280.25,321.875 280.049,321.875 ; 280.049,324.087 280.451,323.684 280.853,324.087 280.451,324.489 280.049,324.087 ; 280.049,325.695 280.25,325.695 280.25,325.494 280.652,325.494 280.652,325.695 280.853,325.695 280.853,326.097 280.652,326.097 280.652,326.299 280.25,326.299 280.25,326.097 280.049,326.097 280.049,325.695 ; 280.049,327.304 280.853,327.304 280.853,328.108 280.049,328.108 280.049,327.304 ; 280.049,329.315 280.25,329.315 280.451,329.114 280.652,329.315 280.853,329.315 280.652,329.516 280.853,329.717 280.652,329.717 280.451,329.918 280.25,329.717 280.049,329.717 280.25,329.516 280.049,329.315 ; 280.049,331.728 280.853,331.728 280.451,330.923 280.049,331.728 ; 280.209,317.089 280.692,317.089 280.451,316.606 280.209,317.089 ; 280.209,327.465 280.692,327.465 280.692,327.947 280.209,327.947 280.209,327.465
  lines w0.305: 279.285,312.283 359.331,312.283 ; 279.285,332.19 359.331,332.19 ; 286.359,310.473 286.359,334 ; 294.481,310.473 294.481,334 ; 311.142,310.473 311.142,334 ; 317.672,310.473 317.672,334 ; 326.952,310.473 326.952,334 ; 345.311,310.473 345.311,334 ; 279.285,310.473 359.331,310.473 359.331,334 279.285,334 279.285,310.473
  text "Symbol" at 280.371,332.733 h0.87
  text "Quantity" at 286.901,332.733 h0.87
  text "Finished Hole Size" at 295.024,332.733 h0.87
  text "Plated" at 311.685,332.733 h0.87
  text "Hole Type" at 318.215,332.733 h0.87
  text "Drill Layer Pair" at 327.495,332.733 h0.87
  text "Hole Tolerance" at 345.854,332.733 h0.87
  text "42" at 286.901,330.923 h0.72
  text "7.87mil (0.200mm)" at 295.024,330.923 h0.72
  text "PTH" at 311.685,330.923 h0.72
  text "Round" at 318.215,330.923 h0.72
  text "Top Layer - Bottom Layer" at 327.495,330.923 h0.72
  text "80" at 286.901,329.114 h0.72
  text "8.00mil (0.203mm)" at 295.024,329.114 h0.72
  text "PTH" at 311.685,329.114 h0.72
  text "Round" at 318.215,329.114 h0.72
  text "(Mixed)" at 327.495,329.114 h0.72
  text "2" at 286.901,327.304 h0.72
  text "10.00mil (0.254mm)" at 295.024,327.304 h0.72
  text "PTH" at 311.685,327.304 h0.72
  text "Round" at 318.215,327.304 h0.72
  text "(Mixed)" at 327.495,327.304 h0.72
  text "68" at 286.901,325.494 h0.72
  text "11.81mil (0.300mm)" at 295.024,325.494 h0.72
  text "PTH" at 311.685,325.494 h0.72
  text "Round" at 318.215,325.494 h0.72
  text "(Mixed)" at 327.495,325.494 h0.72
  text "91" at 286.901,323.684 h0.72
  text "16.00mil (0.406mm)" at 295.024,323.684 h0.72
  text "PTH" at 311.685,323.684 h0.72
  text "Round" at 318.215,323.684 h0.72
  text "(Mixed)" at 327.495,323.684 h0.72
  text "6" at 286.901,321.875 h0.72
  text "20.00mil (0.508mm)" at 295.024,321.875 h0.72
  text "PTH" at 311.685,321.875 h0.72
  text "Round" at 318.215,321.875 h0.72
  text "Top Layer - Bottom Layer" at 327.495,321.875 h0.72
  text "12" at 286.901,320.065 h0.72
  text "30.00mil (0.762mm)" at 295.024,320.065 h0.72
  text "PTH" at 311.685,320.065 h0.72
  text "Round" at 318.215,320.065 h0.72
  text "Top Layer - Bottom Layer" at 327.495,320.065 h0.72
  text "122" at 286.901,318.255 h0.72
  text "40.00mil (1.016mm)" at 295.024,318.255 h0.72
  text "PTH" at 311.685,318.255 h0.72
  text "Round" at 318.215,318.255 h0.72
  text "Top Layer - Bottom Layer" at 327.495,318.255 h0.72
  text "90" at 286.901,316.445 h0.72
  text "40.16mil (1.020mm)" at 295.024,316.445 h0.72
  text "PTH" at 311.685,316.445 h0.72
  text "Round" at 318.215,316.445 h0.72
  text "Top Layer - Bottom Layer" at 327.495,316.445 h0.72
  text "68" at 286.901,314.636 h0.72
  text "47.24mil (1.200mm)" at 295.024,314.636 h0.72
  text "PTH" at 311.685,314.636 h0.72
  text "Round" at 318.215,314.636 h0.72
  text "Top Layer - Bottom Layer" at 327.495,314.636 h0.72
  text "4" at 286.901,312.826 h0.72
  text "125.98mil (3.200mm)" at 295.024,312.826 h0.72
  text "PTH" at 311.685,312.826 h0.72
  text "Round" at 318.215,312.826 h0.72
  text "Top Layer - Bottom Layer" at 327.495,312.826 h0.72
  text "585 Total" at 286.901,311.016 h0.72
  text ".Layer_Name" at 14.656,-21.806 h0.89
M17 Embedded Cavity:
  text ".Layer_Name" at 14.656,-21.806 h0.89
M18 Embedded Assembly:
  text ".Layer_Name" at 14.656,-21.806 h0.89
M19 Embedded Keepout:
  text ".Layer_Name" at 14.402,-21.806 h0.89

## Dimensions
0,-10.16 to 25.4,-10.16 on M2 Board Dimensions
0,0 to 0,0 on M2 Board Dimensions
0,0 to 0,0 on M2 Board Dimensions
